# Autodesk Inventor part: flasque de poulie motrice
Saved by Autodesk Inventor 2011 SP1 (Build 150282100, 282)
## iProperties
Created: 2010-12
Part Number: flasque de poulie motrice
Document SubType Name: Modeling
Designer: eric
Density: 1 g/cm^3
Author: eric
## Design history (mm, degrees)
feature "Base1"
node "Solide1"
node "Corps solides"
node "Corps surfaciques"
